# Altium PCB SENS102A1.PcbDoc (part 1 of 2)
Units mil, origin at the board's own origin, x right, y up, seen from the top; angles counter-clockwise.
Board outline 2760 x 2518.85 mil, 4 copper layers (Top Layer, Signal Layer 1, Signal Layer 2, Bottom Layer), stack 62.2 mil thick; 53 components, 21 nets, 101 pads, 383 vias.
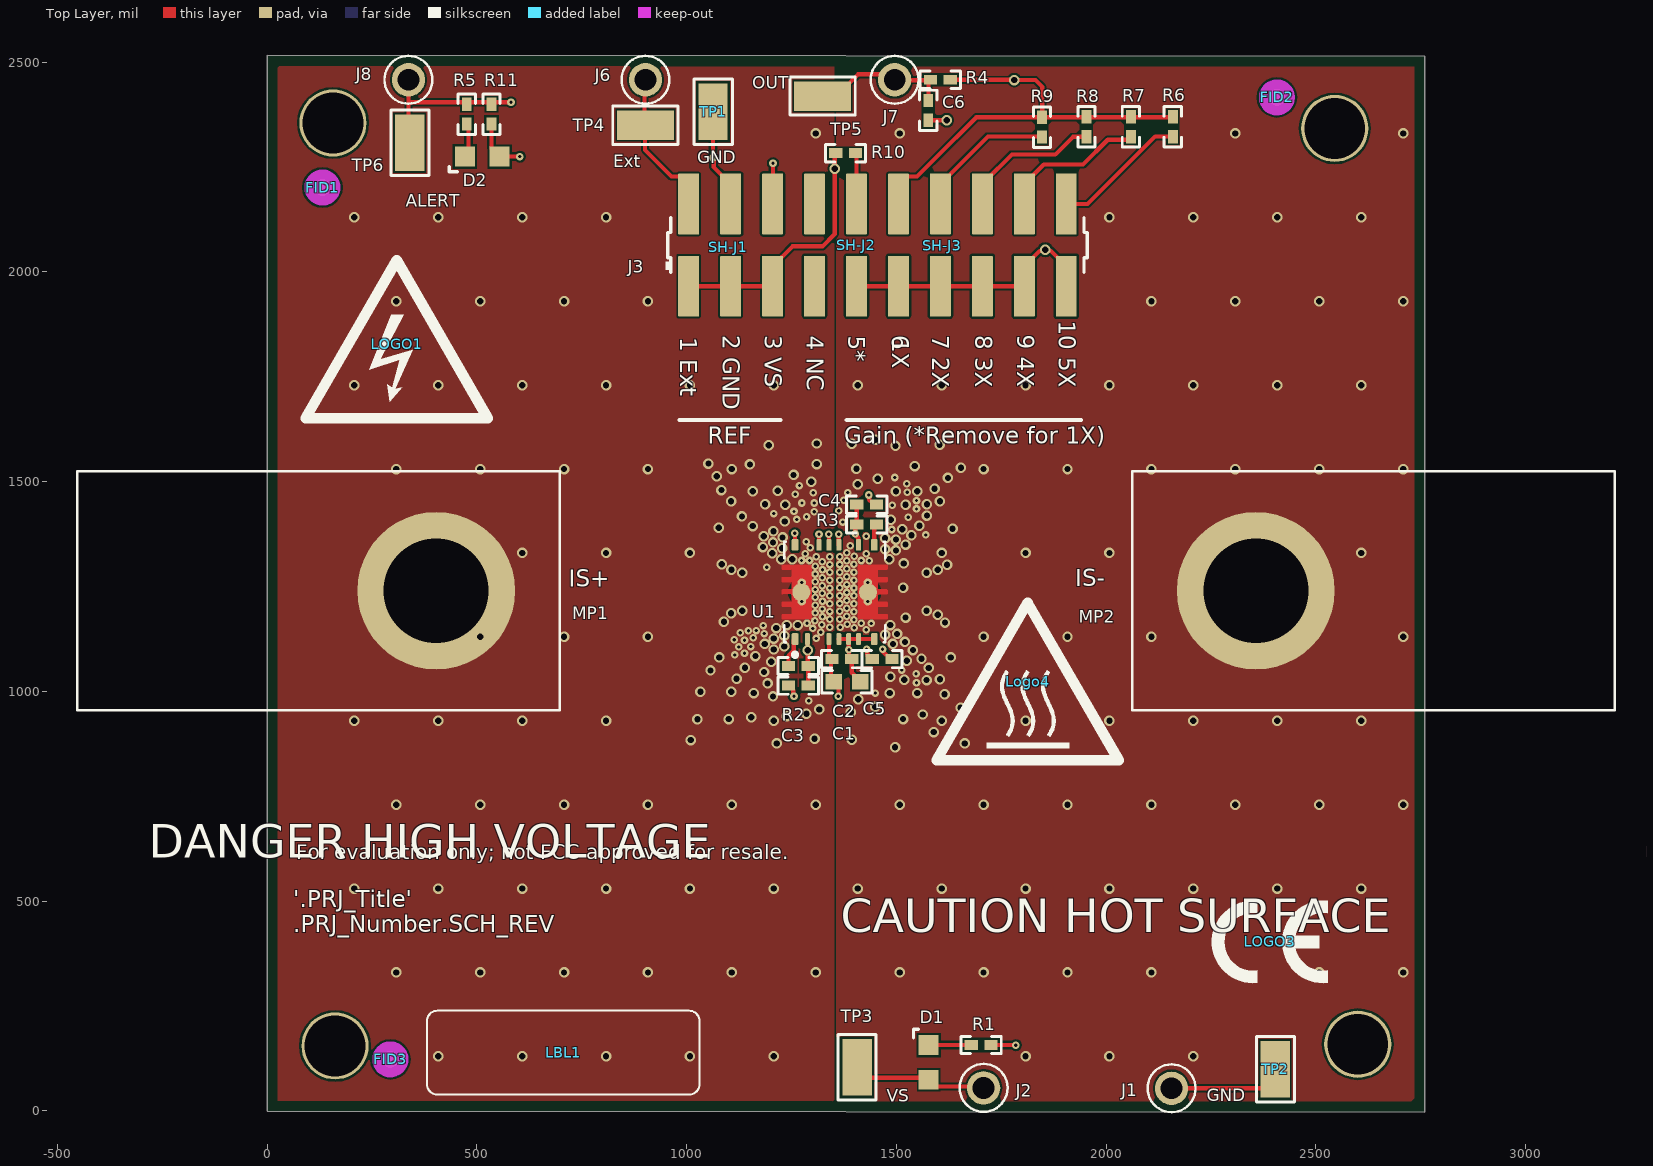
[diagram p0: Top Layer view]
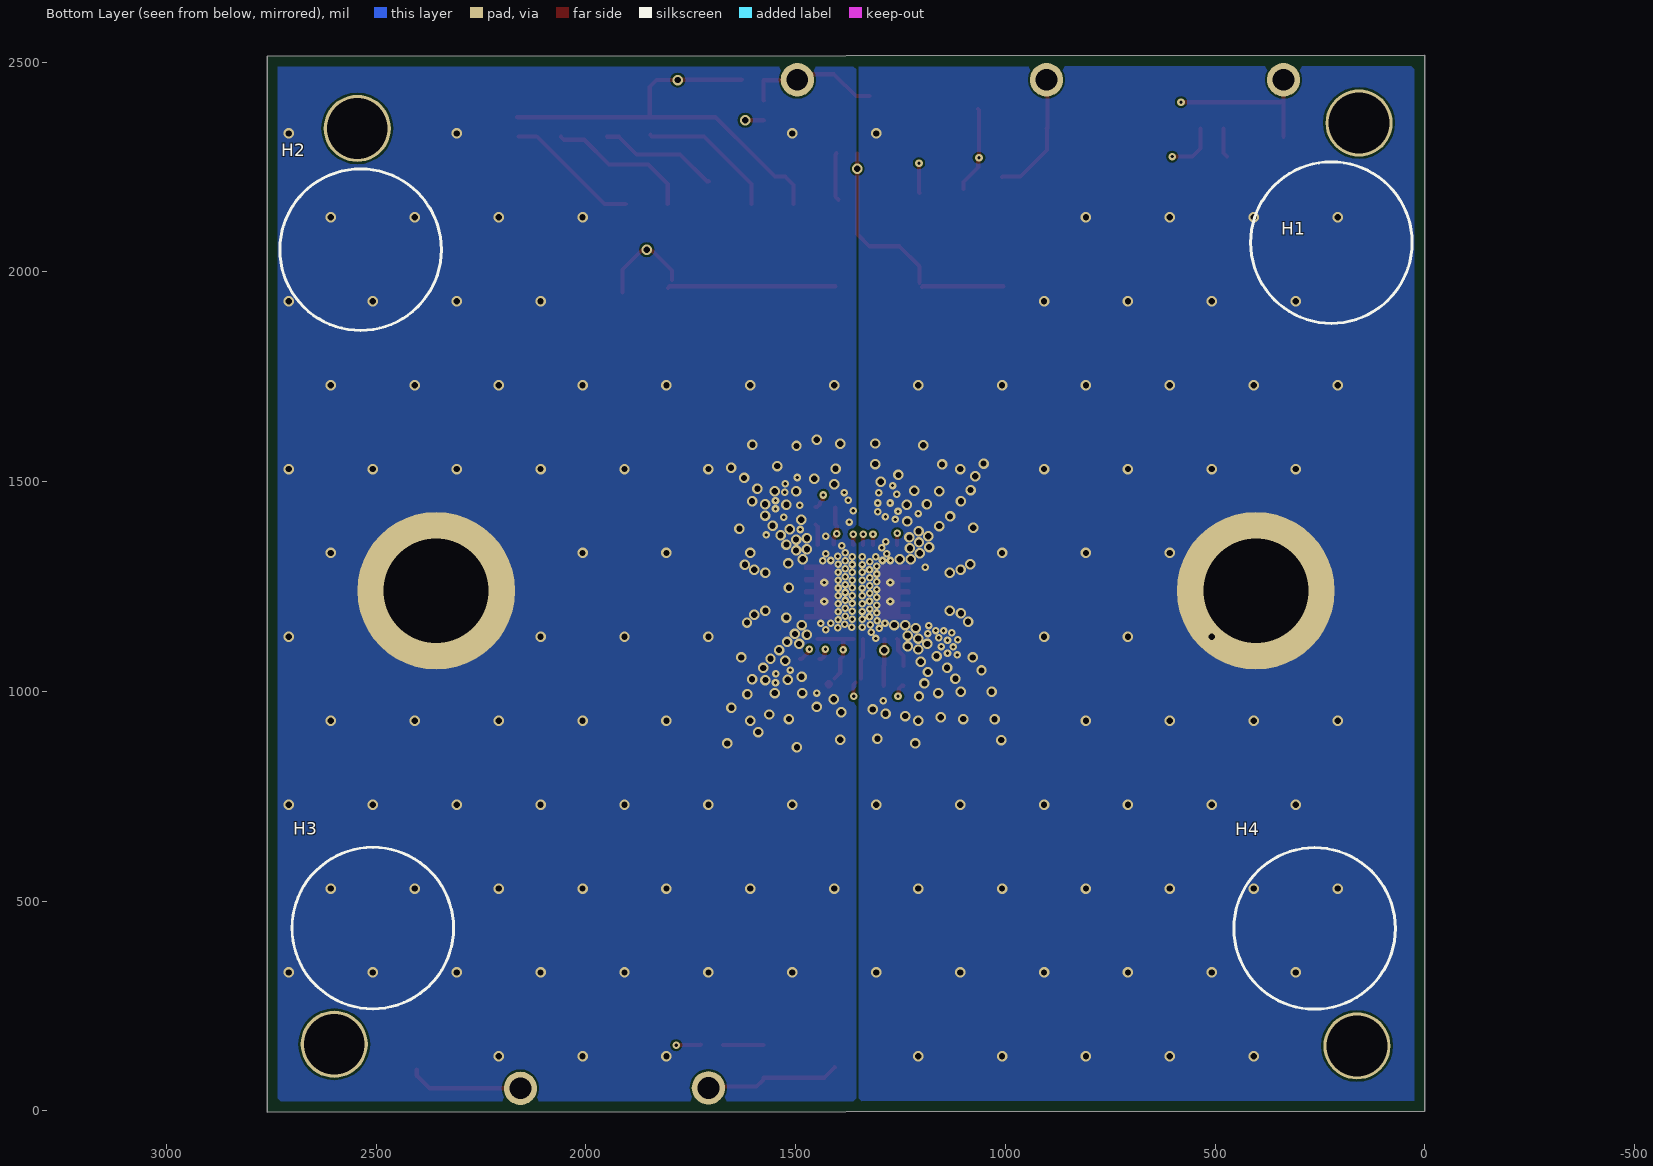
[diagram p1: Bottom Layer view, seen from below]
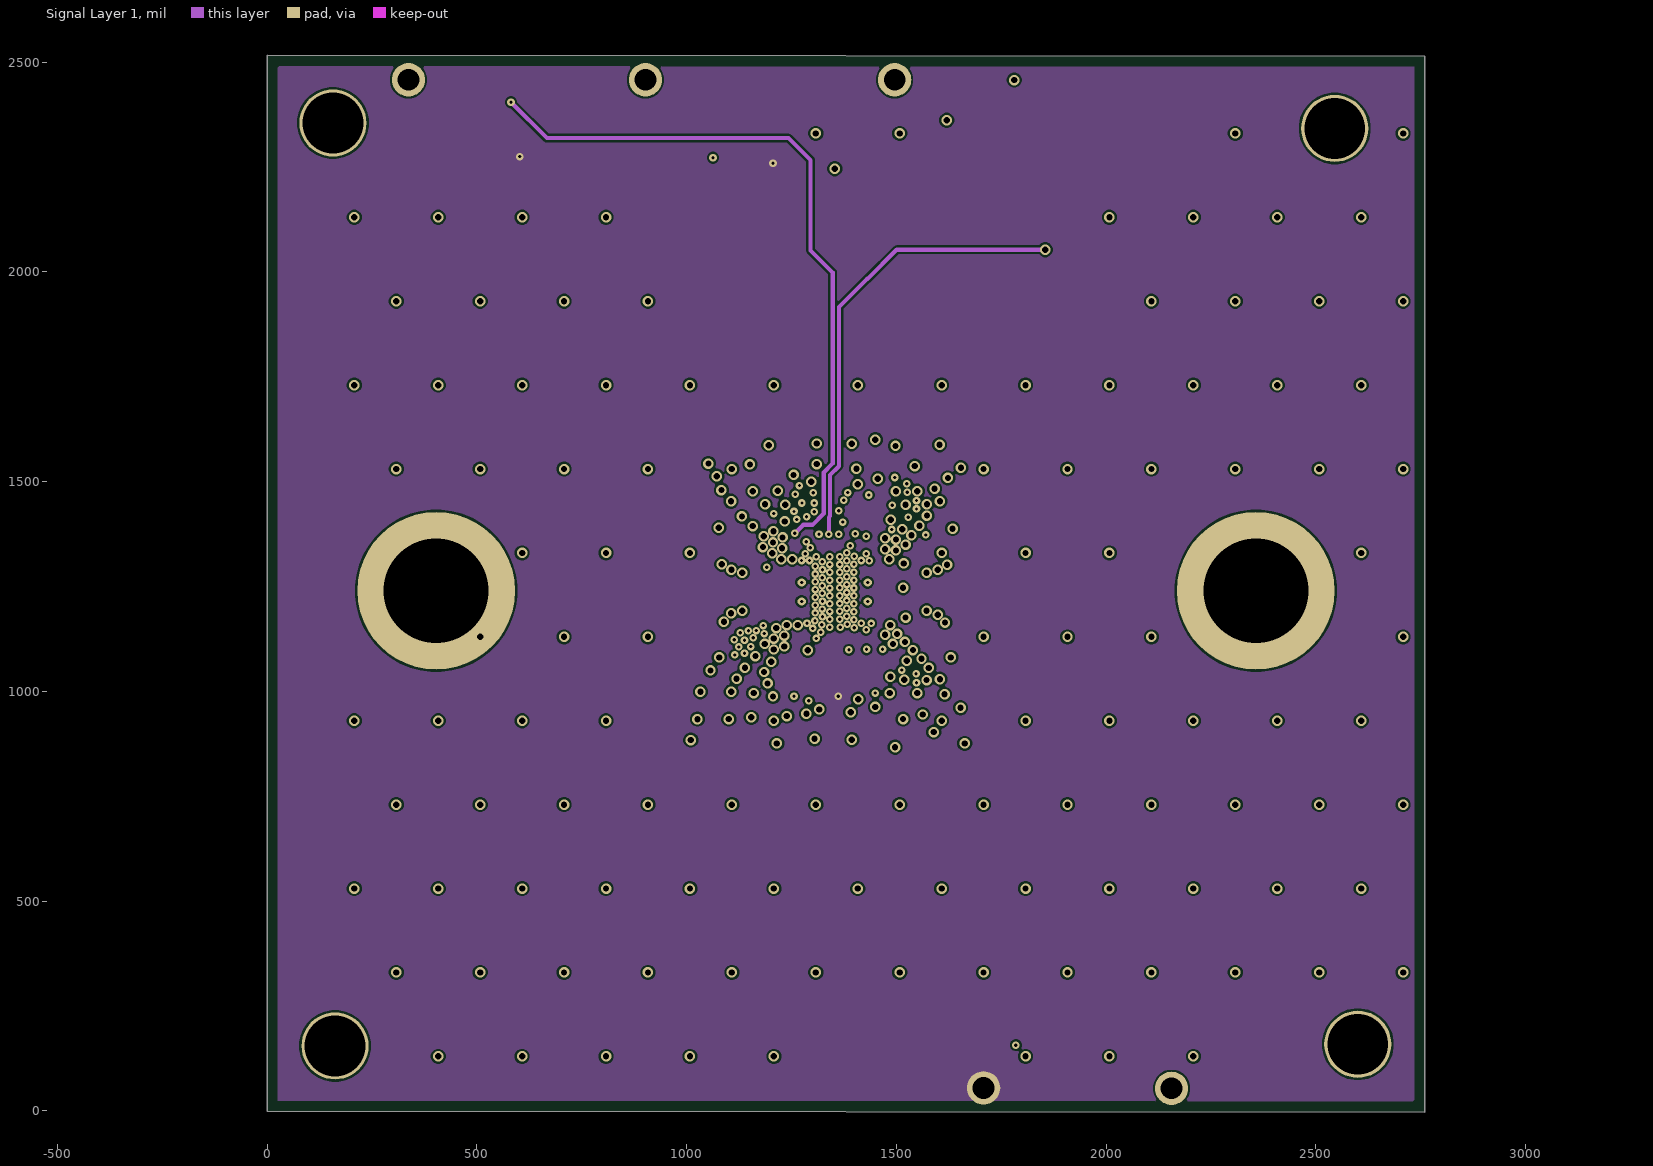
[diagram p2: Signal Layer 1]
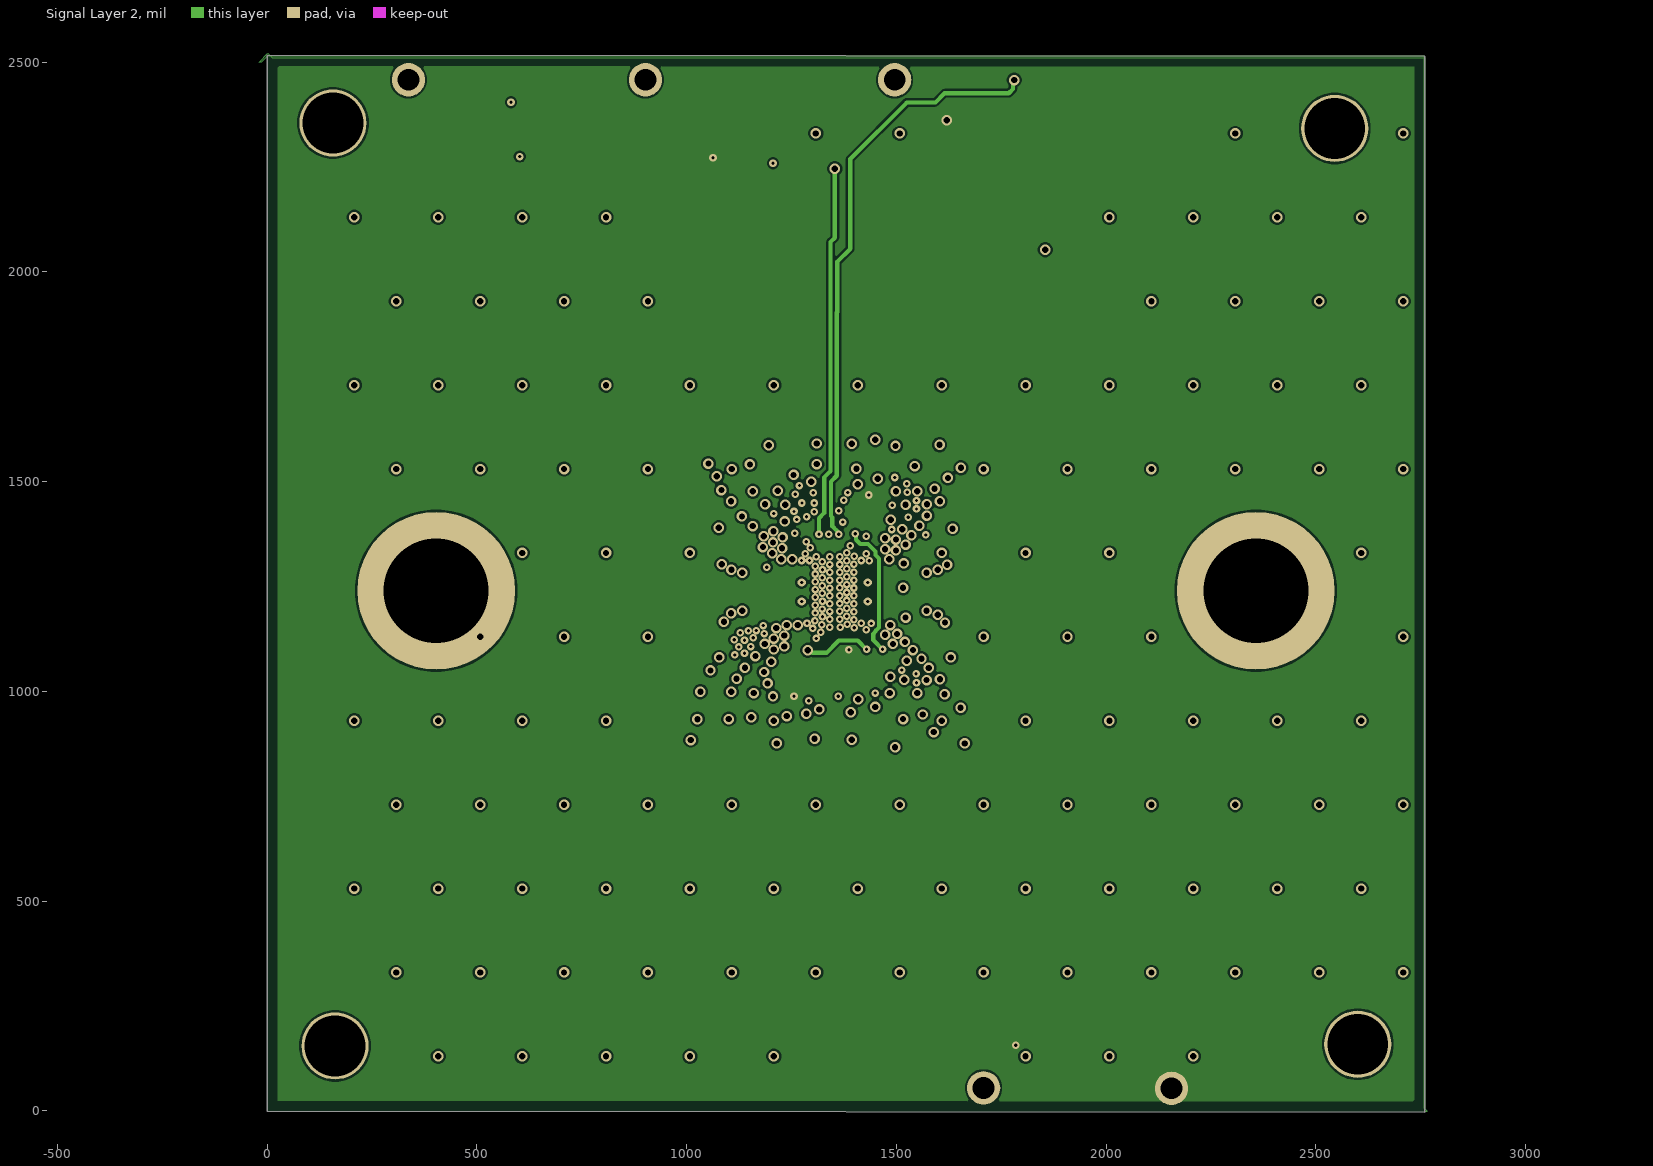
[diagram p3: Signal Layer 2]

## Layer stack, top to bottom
Top Solder: solder mask 0.4, Solder Resist, Dk 3.5
Top Layer: signal copper 2.8
Dielectric1: dielectric 17, FR-4, Dk 4.2
Signal Layer 1: signal copper 2.8
Dielectric 2: core 17, FR-4, Dk 4.2
Signal Layer 2: signal copper 2.8
Dielectric 3: dielectric 17, FR-4, Dk 4.2
Bottom Layer: signal copper 2.8
Bottom Solder: solder mask 0.4, Solder Resist, Dk 3.5

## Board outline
0,-1 0,2516 2760,2514.15 2760,-2.85

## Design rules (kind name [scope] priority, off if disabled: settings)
AcuteAngle [All] p1: minimum=4.50000000000000E+0001 checktracksonly=FALSE
AssemblyTestPointUsage [All] p1: valid=2
BoardOutlineClearance BoardOutlineClearance_MountingHoles [OnCopper and InComponentClass('Mounting Holes')] p1: gap=14 ignorepadtopadclearanceinfootprint=FALSE
BoardOutlineClearance BoardOutlineClearance_Poly [OnCopper and IsPoly] p2: gap=25 ignorepadtopadclearanceinfootprint=FALSE
BoardOutlineClearance [OnCopper and Not InComponentClass('Logo') and not InComponentClass('FiducialMark') and not InRegion(1000,500,4000,800) and not InPoly] p3: gap=15 ignorepadtopadclearanceinfootprint=FALSE
Clearance Clearance_Keepouts [((IsTrack Or IsArc) And Not InPoly) And IsFree and IsKeepOut vs ((IsTrack Or IsArc) And Not InPoly) And IsFree and IsKeepOut] p1: gap=0 ignorepadtopadclearanceinfootprint=FALSE
Clearance Clearance_IS+ [InNet('IS+') vs (InNet('+3V3') OR InNet('+5V') OR InNet('A0') OR InNet('A1') OR InNet('GND') OR InNet('NetD1_2') OR InNet('NetD2_2') OR InNet('NetU1_1') OR InNet('NetU1_7') OR InNet('NetU1_9') OR InNet('PD2') OR InNet('PN4') OR InNet('PN5') OR InNet('PP0'))] p2: gap=5.12 ignorepadtopadclearanceinfootprint=TRUE
Clearance Clearance_IS- [InNet('IS-') vs (InNet('+3V3') OR InNet('+5V') OR InNet('A0') OR InNet('A1') OR InNet('GND') OR InNet('NetD1_2') OR InNet('NetD2_2') OR InNet('NetU1_1') OR InNet('NetU1_7') OR InNet('NetU1_9') OR InNet('PD2') OR InNet('PN4') OR InNet('PN5') OR InNet('PP0'))] p3: gap=5.12 ignorepadtopadclearanceinfootprint=TRUE
Clearance Clearance_FiducialMark [IsKeepOut and InComponentClass('FiducialMark') vs IsPad and InComponentClass('FiducialMark')] p4: gap=0 ignorepadtopadclearanceinfootprint=FALSE
Clearance [All] p5: gap=5 ignorepadtopadclearanceinfootprint=TRUE
ComponentClearance ComponentClearance_MountingHoles_FiducialMarks [InComponentClass('Mounting Holes') vs InComponentClass('FiducialMark')] p1: gap=50 collisioncheckmode=3 verticalgap=10 showdistances=FALSE
ComponentClearance ComponentClearance_Shunt [InComponentClass('Header') vs InComponentClass('Shunt')] p2: gap=0 collisioncheckmode=3 verticalgap=0 showdistances=FALSE
ComponentClearance ComponentClearance_Logo [InComponentClass('Logo')] p3: gap=20 collisioncheckmode=3 verticalgap=10 showdistances=FALSE
ComponentClearance ComponentClearance_ScrewToNut [(HasFootprint('NY PMS 440 0025 PH')) vs (HasFootprint('Keystone_1902C'))] p4: gap=5 collisioncheckmode=3 verticalgap=10 showdistances=FALSE
ComponentClearance ComponentClearance_MountingHoles [InComponentClass('Mounting Holes')] p5: gap=250 collisioncheckmode=3 verticalgap=100000 showdistances=FALSE
ComponentClearance ComponentClearance_SmallPassives [HasFootprint('0201*') or HasFootprint('0402*') or HasFootprint('0508') or HasFootprint('0603*') or HasFootprint('0612') or HasFootprint('0805*') or HasFootprint('0815*') or HasFootprint('0830*') or HasFootprint('1206*') or HasFootprint('1210*') or HasFootprint('1808*') or HasFootprint('1812*') or HasFootprint('1825*') or HasFootprint('2010*') or HasFootprint('2220*') or HasFootprint('2225*') or HasFootprint('2512*') or HasFootprint('2728*') or HasFootprint('3518*') vs HasFootprint('0201*') or HasFootprint('0402*') or HasFootprint('0508') or HasFootprint('0603*') or HasFootprint('0612') or HasFootprint('0805*') or HasFootprint('0815*') or HasFootprint('0830*') or HasFootprint('1206*') or HasFootprint('1210*') or HasFootprint('1808*') or HasFootprint('1812*') or HasFootprint('1825*') or HasFootprint('2010*') or HasFootprint('2220*') or HasFootprint('2225*') or HasFootprint('2512*') or HasFootprint('2728*') or HasFootprint('3518*')] p6: gap=14.96 collisioncheckmode=3 verticalgap=10 showdistances=FALSE
ComponentClearance ComponentClearance_THtoSMT [IsThruComponent vs IsSMTComponent] p7: gap=40 collisioncheckmode=3 verticalgap=30 showdistances=FALSE
ComponentClearance ComponentClearance_THtoTH [IsThruComponent vs IsThruComponent] p8: gap=30 collisioncheckmode=3 verticalgap=30 showdistances=FALSE
ComponentClearance [All] p9: gap=30 collisioncheckmode=3 verticalgap=10 showdistances=FALSE
DiffPairsRouting [All] p1: maxlimit=100 minlimit=10 mostfreqgap=10 toplayer_minwidth=15 toplayer_maxwidth=15 toplayer_prefwidth=15 midlayer1_minwidth=15 midlayer1_maxwidth=15 midlayer1_prefwidth=15 midlayer2_minwidth=15 midlayer2_maxwidth=15 midlayer2_prefwidth=15 bottomlayer_minwidth=15 bottomlayer_maxwidth=15 bottomlayer_prefwidth=15 maxuncoupledlength=1000
FabricationTestPointUsage TestPointUsage [All] p1: valid=2 allowmultiple=FALSE
FabricationTestpoint Testpoint [All] p1: side=3 testpointundercomponent=TRUE minsize=40 maxsize=100 preferedsize=60 minholesize=0 maxholesize=40 preferedholesize=32 testpointgrid=1 allowsidetop=TRUE allowsidebottom=TRUE usegrid=TRUE gridtolerance=0.01
FanoutControl Fanout_LCC [IsLCC] p1: bgadir=Out bgaviamode=Centered fanoutstyle=Auto fanoutdirection=Alternating viagrid=1 // Fanout_LCC (Default Rule)
FanoutControl Fanout_BGA [IsBGA] p2: bgadir=Out bgaviamode=Centered fanoutstyle=Auto fanoutdirection=Alternating viagrid=1 // Fanout_BGA (Default Rule)
FanoutControl Fanout_Default [All] p4: bgadir=Out bgaviamode=Centered fanoutstyle=Auto fanoutdirection=Alternating viagrid=1 // Fanout_Default (Default Rule)
FanoutControl Fanout_Small [(CompPinCount < 5)] p5: bgadir=Out bgaviamode=Centered fanoutstyle=Auto fanoutdirection=OutThenIn viagrid=1 // Fanout_Small (Default Rule)
HoleSize [All] p1: absolutevalues=TRUE maxlimit=251 minlimit=8 maxpercent=80.000 minpercent=20.000
HoleToHoleClearance [All] p1: gap=8 allowstackedmicrovias=TRUE
MinimumAnnularRing MinimumAnnularRing_ThermalPadVias [IsVia and InAnyComponent] p1: minimumring=5
MinimumAnnularRing [All] p2: minimumring=5
MinimumSolderMaskSliver MinimumSolderMaskSliver_Logo [InComponentClass('Logo') vs InComponentClass('Logo')] p1: minsoldermaskwidth=0.7
MinimumSolderMaskSliver [All] p2: minsoldermaskwidth=4
PlaneConnect [All] p1: planeconnectstyle=Relief reliefexpansion=10 reliefentries=4 reliefconductorwidth=10 reliefairgap=10
PolygonConnect PolygonConnect_Trace [InNet('NetJ1_5') OR InNet('NetJ1_3')] p1: connectstyle=Direct reliefconductorwidth=10 reliefentries=4 polygonreliefangle="90 Angle" airgapwidth=10
PolygonConnect [All] p2: thpad.connectstyle=Direct thpad.reliefconductorwidth=10 thpad.reliefentries=4 thpad.polygonreliefangle="90 Angle" thpad.airgapwidth=10 smdpad.connectstyle=Relief smdpad.reliefconductorwidth=10 smdpad.reliefentries=2 smdpad.polygonreliefangle="90 Angle" smdpad.airgapwidth=10 via.connectstyle=Direct via.reliefconductorwidth=10 via.reliefentries=4 via.polygonreliefangle="90 Angle" via.airgapwidth=10
RoutingVias [All] p1: holewidth=10 width=20 viastyle="Through Hole" minholewidth=4 minwidth=15 maxholewidth=40 maxwidth=65
SilkToBoardRegionClearance [Not ((IsComment or IsDesignator) And (Hide <> 'False')) and not InRegion(1000,500,4000,800)] p1:
SilkToSilkClearance SilkToSilkClearance_Pb-FreeLogo [(HasFootprint('Pb-Free_Overlay_Medium') OR HasFootprint('Pb-Free_Overlay_Small')) vs (HasFootprint('Pb-Free_Overlay_Medium') OR HasFootprint('Pb-Free_Overlay_Small'))] p1: silktosilkclearance=0
SilkToSilkClearance [All] p2: silktosilkclearance=3.94
SilkToSolderMaskClearance SilkToComponentPadClearance [(IsPad or IsFill or IsRegion) and InAnycomponent] p1: minsilkscreentomaskgap=5 clearancetoexposedcopper=TRUE
SilkToSolderMaskClearance "Silk to Solder Mask Opening" [All] p2: minsilkscreentomaskgap=3.94 clearancetoexposedcopper=FALSE
SolderMaskExpansion [All] p1: expansion=1.97 istentingtop=FALSE
UnRoutedNet [All] p1: checkbadconnections=TRUE
Width [All] p1: maxlimit=100 minlimit=5 preferedwidth=10 checkconnectedcopper=TRUE
13 further rules are at their usual default settings.

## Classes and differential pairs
component class Label: LBL1
component class Shunt: SH-J1 SH-J2 SH-J3
component class Header: J3
component class SENS102E1: "ALERT BUS" C1 C2 C3 C4 C5 C6 D1 D2 J1 J2 J3 J6 J7 J8 MP1 MP2 q R1 R2 R3 R4 R5 R6 R7 R8 R9 R10 R11 SH-J1 SH-J2 SH-J3 SW2 SW? TP1 TP2 TP3 TP4 TP5 TP6 U1
component class SENS102E1_HW: FID1 FID2 FID3 H1 H2 H3 H4 LBL1 LOGO1 Logo2 LOGO3 Logo4 ZZ1 ZZ2 ZZ3 ZZ4
component class FiducialMark: FID1 FID2 FID3
component class AssemblyNote: ZZ1 ZZ2 ZZ3 ZZ4

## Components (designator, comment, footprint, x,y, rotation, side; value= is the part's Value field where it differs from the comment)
C1 "C1608X6S1H105K080AC" 0603 1382.19,1023 r0 top value=1uF
C2 "GRM155R71H104ME14D" 0402 1370,1077 r0 top value=0.1uF
C3 "CGA2B3X7S2A103K050BB" 0402 1266.25,1013.71 r180 top value=0.01uF
C4 "CGA2B3X7S2A103K050BB" 0402 1429.36,1445.12 r0 top value=0.01uF
C5 "CGA2B3X7S2A103K050BB" 0402 1466,1077 r0 top value=0.01uF
C6 "CGA2B3X7S2A103K050BB" 0402 1576,2385 r90 top value=0.01uF
D1 "POWER" VAOL-0805_White 1577,115.66 r90 top
D2 "ALERT" VAOL-0805_White 513,2275 r180 top
FID1 "Fiducial" Fiducial10-20 132,2201.12 r0 top
FID2 "Fiducial" Fiducial10-20 2407,2416 r0 top
FID3 "Fiducial" Fiducial10-20 294,123 r0 top
H1 "SJ61A2" Bumpon_SJ61A2 223,2070 r180 bottom
H2 "SJ61A2" Bumpon_SJ61A2 2537,2053 r180 bottom
H3 "SJ61A2" Bumpon_SJ61A2 2508,436 r180 bottom
H4 "SJ61A2" Bumpon_SJ61A2 263,435 r180 bottom
J1 "" FP-3-331272-8_PIN_RCPT-MFG 2156,54 r0 top
J2 "" FP-3-331272-8_PIN_RCPT-MFG 1708,55 r180 top
J3 "TSM-110-01-L-DV-P" CONN_TSM-110-01-T-DV-P 1455,2064 r90 top
J6 "" FP-3-331272-8_PIN_RCPT-MFG 902,2458 r0 top
J7 "" FP-3-331272-8_PIN_RCPT-MFG 1496,2458 r0 top
J8 "" FP-3-331272-8_PIN_RCPT-MFG 337,2458 r0 top
LBL1 "THT-14-423-10" Label_650x200 706,139 r180 top
LOGO1 "DANGER HIGH VOLTAGE" IEC_HighVoltage_Medium 309,1827 r0 top
Logo2 "FCC disclaimer" FCC_disclaimer 3340,617.12 r90 top
LOGO3 "CE Mark" CE_Mark_5mm 2390,403 r0 top
Logo4 "CAUTION HOT SURFACE" IEC_HotSurface_Medium 1813,1023 r0 top
MP1 "LAMA6-14-QY" FP-LAMA6-14-QY_TERMINAL_CONN-MFG 123,1240 r0 top
MP2 "LAMA6-14-QY" FP-LAMA6-14-QY_TERMINAL_CONN-MFG 2637,1240 r180 top
R1 "CRCW040210K0FKED" 0402 1702,157 r180 top value=10.0k
R2 "RC0402JR-070RL" 0402 1266.25,1060.71 r0 top value=0
R3 "RC0402JR-070RL" 0402 1429.36,1398 r180 top value=0
R4 "RC0402JR-070RL" 0402 1605,2458 r180 top value=0
R5 "CRCW040210K0FKED" 0402 476,2376 r90 top value=10.0k
R6 "CRCW040220K0FKED" 0402 2159,2346 r270 top value=20.0k
R7 "CRCW040215K0FKED" 0402 2059,2346 r270 top value=15.0k
R8 "CRCW040210K0FKED" 0402 1953,2346 r90 top value=10.0k
R9 "CRCW04024K99FKED" 0402 1847,2345 r270 top value=4.99k
R10 "CRCW04024K99FKED" 0402 1379,2283 r0 top value=4.99k
R11 "CRCW040210K0FKED" 0402 535,2376 r90 top value=10.0k
SH-J1 "SPC02SYAN" SPC02SYAN 1099,2059 r270 top value=1x2
SH-J2 "SPC02SYAN" SPC02SYAN 1404,2063 r90 top value=1x2
SH-J3 "SPC02SYAN" SPC02SYAN 1610,2062 r90 top value=1x2
TP1 "GND" Testpoint_Keystone_Miniature 1063,2382 r90 top
TP2 "GND" Testpoint_Keystone_Miniature 2403,99 r90 top
TP3 "VS" Testpoint_Keystone_Miniature 1407,104 r270 top
TP4 "Ext_REF" Testpoint_Keystone_Miniature 902,2350 r0 top
TP5 "OUT" Testpoint_Keystone_Miniature 1324,2419 r180 top
TP6 "" Testpoint_Keystone_Miniature 340,2308 r90 top
U1 "INA790AIDEKR" DEK0015A-MFG 1353,1237.12 r90 top
ZZ1 "This Assembly Note is for PCB labels only" AssemblyNoteLabel -115,3802.12 r0 top
ZZ2 "These assemblies are ESD sensitive, ESD precautions shall be observed." AssemblyNote -115,3693.24 r0 top
ZZ3 "These assemblies must be clean and free from flux and all contaminants. Use of no clean flux is not acceptable." AssemblyNote -115,3604.68 r0 top
ZZ4 "These assemblies must comply with workmanship standards IPC-A-610 Class 2, unless otherwise specified." AssemblyNote -115,3516.12 r0 top

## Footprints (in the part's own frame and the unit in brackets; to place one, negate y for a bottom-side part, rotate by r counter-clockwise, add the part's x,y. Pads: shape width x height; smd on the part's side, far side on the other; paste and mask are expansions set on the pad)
0402 [mm] "0402 from SM-752 data"
  rect 0.8x0.6 smd: 1(-0.6,0) 2(0.6,0)
  silkscreen extent -1.22,-0.52 1.22,0.52, body extent -0.55,-0.3 0.55,0.3, height 0.6
0603 [mm] "0603 from SM-752 data"
  rect 1x0.95 smd: 1(-0.8,0) 2(0.8,0)
  silkscreen extent -1.52,-0.69 1.52,0.69, body extent -0.87,-0.47 0.87,0.47, height 1
AssemblyNote [mil] "Assembly Note"
AssemblyNoteLabel [mil] "Assembly Note for PCB Labels"
Bumpon_SJ61A2 [mil] "3M Hemispherical Bumpon transparent"
  round 1 on Mech4: 0(0,0)
  silkscreen extent -192,-192 192,192, body extent -193,-193 193,193, height 250
CE_Mark_5mm [mil] "Minimum text height for CE Mark"
  silkscreen extent -138,-98 138,98
CONN_TSM-110-01-T-DV-P [mil]
  rrect8% 145x50 smd: 1(-98,450) 2(98,450) 3(-98,350) 4(98,350) 5(-98,250) 6(98,250) 7(-98,150) 8(98,150) 9(-98,50) 10(98,50) 11(-98,-50) 12(98,-50) 13(-98,-150) 14(98,-150) 15(-98,-250) 16(98,-250) 17(-98,-350) 18(98,-350) 19(-98,-450) 20(98,-450)
  silkscreen extent -65,-500 65,506, body extent -145,-500 145,500, height 380
DEK0015A-MFG [mm]
  rrect25% 0.7x0.4 smd paste+0 mask+0: 1(-2.85,2.4) 7(-2.85,-2.4) 9(2.85,-2.4) 14(2.85,2.4)
  rrect33% 0.7x0.3 smd paste+0 mask+0: 2(-2.85,1.65) 3(-2.85,0.35) 4(-2.85,-0.25) 5(-2.85,-0.85) 6(-2.85,-1.45) 10(2.85,-1.45) 11(2.85,-0.25) 12(2.85,0.35) 13(2.85,0.95)
  round 1.092 smd paste-1000 mask+0: 8(-0.019,-2.019) 15(-0.019,2.019)
  Top Layer region: 1.65,-3.15 1.643,-3.175 1.625,-3.193 1.6,-3.2 1.6,-3.2 1.4,-3.2 1.375,-3.193 1.357,-3.175 1.35,-3.15 1.35,-3.15 1.35,-2.65 1.346,-2.631 1.335,-2.615 1.319,-2.604 1.3,-2.6 1.3,-2.6 0.95,-2.6 0.931,-2.604 0.915,-2.615 0.904,-2.631 0.9,-2.65 0.9,-2.65 0.9,-3.15 0.893,-3.175 0.875,-3.193 0.85,-3.2 0.85,-3.2 0.65,-3.2 0.631,-3.196 0.615,-3.185 0.604,-3.169 0.6,-3.15 0.6,-3.15 0.6,-2.65 0.596,-2.631 0.585,-2.615 0.569,-2.604 0.55,-2.6 0.55,-2.6 0.2,-2.6 0.181,-2.604 0.165,-2.615 0.154,-2.631 0.15,-2.65 0.15,-2.65 0.15,-3.15 0.143,-3.175 0.125,-3.193 0.1,-3.2 0.1,-3.2 -0.1,-3.2 -0.125,-3.193 -0.143,-3.175 -0.15,-3.15 -0.15,-3.15 -0.15,-2.65 -0.154,-2.631 -0.165,-2.615 -0.181,-2.604 -0.2,-2.6 -0.2,-2.6 -0.55,-2.6 -0.569,-2.604 -0.585,-2.615 -0.596,-2.631 -0.6,-2.65 -0.6,-2.65 -0.6,-3.15 -0.604,-3.169 -0.615,-3.185 -0.631,-3.196 -0.65,-3.2 -0.65,-3.2 -0.85,-3.2 -0.869,-3.196 -0.885,-3.185 -0.896,-3.169 -0.9,-3.15 -0.9,-3.15 -0.9,-2.65 -0.904,-2.631 -0.915,-2.615 -0.931,-2.604 -0.95,-2.6 -0.95,-2.6 -1.3,-2.6 -1.319,-2.604 -1.335,-2.615 -1.346,-2.631 -1.35,-2.65 -1.35,-2.65 -1.35,-3.15 -1.354,-3.169 -1.365,-3.185 -1.381,-3.196 -1.4,-3.2 -1.4,-3.2 -1.6,-3.2 -1.625,-3.193 -1.643,-3.175 -1.65,-3.15 -1.65,-3.15 -1.65,-1.45 -1.643,-1.425 -1.625,-1.407 -1.6,-1.4 -1.6,-1.4 1.6,-1.4 1.625,-1.407 1.643,-1.425 1.65,-1.45 1.65,-1.45
  Top Layer region: -1.65,3.15 -1.643,3.175 -1.625,3.193 -1.6,3.2 -1.6,3.2 -1.4,3.2 -1.375,3.193 -1.357,3.175 -1.35,3.15 -1.35,3.15 -1.35,2.65 -1.346,2.631 -1.335,2.615 -1.319,2.604 -1.3,2.6 -1.3,2.6 -0.95,2.6 -0.931,2.604 -0.915,2.615 -0.904,2.631 -0.9,2.65 -0.9,2.65 -0.9,3.15 -0.893,3.175 -0.875,3.193 -0.85,3.2 -0.85,3.2 -0.65,3.2 -0.631,3.196 -0.615,3.185 -0.604,3.169 -0.6,3.15 -0.6,3.15 -0.6,2.65 -0.596,2.631 -0.585,2.615 -0.569,2.604 -0.55,2.6 -0.55,2.6 -0.2,2.6 -0.181,2.604 -0.165,2.615 -0.154,2.631 -0.15,2.65 -0.15,2.65 -0.15,3.15 -0.143,3.175 -0.125,3.193 -0.1,3.2 -0.1,3.2 0.1,3.2 0.125,3.193 0.143,3.175 0.15,3.15 0.15,3.15 0.15,2.65 0.154,2.631 0.165,2.615 0.181,2.604 0.2,2.6 0.2,2.6 0.55,2.6 0.569,2.604 0.585,2.615 0.596,2.631 0.6,2.65 0.6,2.65 0.6,3.15 0.604,3.169 0.615,3.185 0.631,3.196 0.65,3.2 0.65,3.2 0.85,3.2 0.869,3.196 0.885,3.185 0.896,3.169 0.9,3.15 0.9,3.15 0.9,2.65 0.904,2.631 0.915,2.615 0.931,2.604 0.95,2.6 0.95,2.6 1.3,2.6 1.319,2.604 1.335,2.615 1.346,2.631 1.35,2.65 1.35,2.65 1.35,3.15 1.354,3.169 1.365,3.185 1.381,3.196 1.4,3.2 1.4,3.2 1.6,3.2 1.625,3.193 1.643,3.175 1.65,3.15 1.65,3.15 1.65,1.45 1.643,1.425 1.625,1.407 1.6,1.4 1.6,1.4 -1.6,1.4 -1.625,1.407 -1.643,1.425 -1.65,1.45 -1.65,1.45
  silkscreen extent -3.92,-3.05 3.05,3.05, body extent -3.3,-3.3 3.3,3.3, height 0.25
FCC_disclaimer [mil]
Fiducial10-20 [mm]
  round 1 smd mask+0.5: 1(0,0)
  Top Layer keep-out circle w1.178: c0,0 r0.5
FP-3-331272-8_PIN_RCPT-MFG [mm]
  round 2.02 hole 1.32 paste-1000 mask+0: 1(0,0)
  silkscreen extent -1.45,-1.45 1.45,1.45, body extent -1.11,-1.11 1.11,1.11, height 0.25
FP-LAMA6-14-QY_TERMINAL_CONN-MFG [mm]
  round 9.55 hole 6.35 paste-1000 mask+0: 1(7.112,0)
  silkscreen extent -14.6,-7.24 14.6,7.24, body extent -14.32,-6.96 14.32,6.96, height 0.25
IEC_HighVoltage_Medium [mil]
  silkscreen extent -217,-176 217,200
IEC_HotSurface_Medium [mil]
  silkscreen extent -217,-188 217,188
Label_650x200 [mil] "Thermal Transfer Label"
  round 1 on Mech13: 0(0,0)
  silkscreen extent -325,-100 325,100, body extent -325,-100 325,100, height 1
SPC02SYAN [mil] "SULLINS"
  round 1 on Mech3: 0(0,0)
  body extent -98,-47 99,47, height 366
Testpoint_Keystone_Miniature [mil] "Miniature SMT test point"
  rect 135x70 smd: 1(0,0)
  silkscreen extent -78,-46 78,45, body extent -52,-20 52,20, height 61
VAOL-0805_White [mm] "Visual Communications"
  rect 1.2x1.2 smd: 1(-1.05,0) 2(1.05,0)
  silkscreen extent 1.5,0.63 2,0.91, body extent -1.05,-0.67 1.05,0.67, height 1.1

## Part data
C1: library part CMP-0007029-4, "CAP, CERM, 1 uF, 50 V, +/- 10%, X6S, 0603", Cap_Case=0603, Manufacturer=TDK, Supplier Part Number 1=445-7424-1-ND, TempCo=X6S, Tolerance_%=10%, Value1="0.005522 ohm", Value2=50V, ValueDisplayed=1uF
C2: library part CMP-0006675-2, "CAP, CERM, 0.1 uF, 50 V, +/- 20%, X7R, 0402", Cap_Case=0402, Manufacturer=MuRata, Supplier Part Number 1=490-10701-1-ND, TempCo=X7R, Tolerance_%=20%, Value1=Unknown, Value2=50V, ValueDisplayed=0.1uF
C3 C4 C5 C6: library part CMP-0006333-1, "CAP, CERM, 0.01 uF, 100 V, +/- 10%, X7S, AEC-Q200 Grade 1, 0402", Cap_Case=0402, Manufacturer=TDK, Supplier Part Number 1=445-6910-1-ND, TempCo=X7S, Tolerance_%=10%, Value1="0.410191 ohm", Value2=100V, ValueDisplayed=0.01uF
D1 D2: library part CMP-0002885-2, "LED, White, SMD", Color=White, Manufacturer="Visual Communications Company, LLC", PartNumber=VAOL-S8WR4, Value1=W, Value2=2.925V
FID1 FID2 FID3: library part CMP-0077181-1, "Fiducial mark.  There is nothing to buy or mount.", Manufacturer=N/A
H1 H2 H3 H4: library part CMP-0003622-1, "Bumpon, Hemisphere, 0.375 X 0.235, Black", Manufacturer=3M, Supplier Part Number 1=SJ5748-0-ND
J1 J2 J6 J7 J8: library part CMP-0086763-1, "CONN PIN RCPT .018-.021 SOLDER", Current_A=5A, Manufacturer="TE Connectivity", PartNumber=3-331272-8
J3: library part CMP-0075600-2, "Header, 2.54mm, 10x2, Gold, SMT", Color=Black, Current_A=5.4A, Manufacturer=Samtec, Supplier Part Number 1=SAM8739-ND, Voltage_V=475V
LBL1: library part CMP-0003625-1, "Thermal Transfer Printable Labels, 0.650\" W x 0.200\" H - 10,000 per roll", Manufacturer=Brady, Supplier Part Number 1=97C5133
LOGO1: library part CMP-0074835-1, "IEC 61010-1 High Voltage Warning"
Logo2: library part CMP-0074847-1, "FCC_disclaimer"
LOGO3: library part CMP-0074844-1
Logo4: library part CMP-0074837-2, "IEC 61010-1 Hot Surface Warning", Manufacturer="Texas Instruments"
MP1 MP2: library part CMP-0091352-2, "Terminal Connector Rectangular Lug, Grounding 6-14 AWG 1/4 Stud", Digikey Part Number=298-10102-ND, Manufacturer=Panduit, Mouser Part Number=644-LAMA6-14-QY, Operating Temperature Range=to
R1 R5 R8 R11: library part CMP-0025958-3, "RES, 10.0 k, 1%, 0.063 W, AEC-Q200 Grade 0, 0402", Manufacturer=Vishay-Dale, Power_W=63mW, Supplier Part Number 1=541-10.0KLCT-ND, TempCo="100 ppm/C", Tolerance_%=1%, Value2=0.063W, Value_Code=10k0, ValueDisplayed=10.0k
R2 R3 R4: library part CMP-0027004-2, "RES, 0, 5%, 0.063 W, 0402", Manufacturer="Yageo America", Power_W=63mW, Supplier Part Number 1=311-0.0JRCT-ND, TempCo="200 ppm/C", Tolerance_%=5%, Value2=0.063W, Value_Code=0000, ValueDisplayed=0
R6: library part CMP-0026162-1, "RES, 20.0 k, 1%, 0.063 W, 0402", Manufacturer=Vishay-Dale, Power_W=63mW, Supplier Part Number 1=541-20.0KLCT-ND, TempCo="100 ppm/C", Tolerance_%=1%, Value2=0.063W, Value_Code=20k0, ValueDisplayed=20.0k
R7: library part CMP-0026027-2, "RES, 15.0 k, 1%, 0.063 W, 0402", Manufacturer=Vishay-Dale, Power_W=63mW, Supplier Part Number 1=541-15.0KLCT-ND, TempCo="100 ppm/C", Tolerance_%=1%, Value2=0.063W, Value_Code=15k0, ValueDisplayed=15.0k
R9 R10: library part CMP-0026414-1, "RES, 4.99 k, 1%, 0.063 W, 0402", Manufacturer=Vishay-Dale, Power_W=63mW, Supplier Part Number 1=541-4.99KLCT-ND, TempCo="100 ppm/C", Tolerance_%=1%, Value2=0.063W, Value_Code=4k99, ValueDisplayed=4.99k
SH-J1 SH-J2 SH-J3: library part CMP-0003642-1, "Shunt, 100mil, Flash Gold, Black", Manufacturer="Sullins Connector Solutions", Supplier Part Number 1=S9001-ND
TP1 TP2 TP3 TP4 TP5 TP6: library part CMP-0055152-1, "Test Point, Miniature, SMT", Manufacturer=Keystone, PartNumber=5015, Supplier Part Number 1=36-5015TR-ND
U1: library part CMP-0034221-1, Manufacturer="Texas Instruments", Operating Temperature Range=to
ZZ1: library part CMP-0003616-3
ZZ2: library part CMP-0077236-1
ZZ3: library part CMP-0077237-1
ZZ4: library part CMP-0077238-1

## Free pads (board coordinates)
  round 160 hole 145: 3(157,2355) 3(162,155) 3(2545,2342.12) 3(2600,159)

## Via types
v1: diameter 25, hole 15, Top Layer to Bottom Layer, tented both sides, 247 vias
v2: diameter 18, hole 8, Top Layer to Bottom Layer, tented both sides, 132 vias
v3: diameter 19.68, hole 7.87, Top Layer to Bottom Layer, tented both sides, 4 vias

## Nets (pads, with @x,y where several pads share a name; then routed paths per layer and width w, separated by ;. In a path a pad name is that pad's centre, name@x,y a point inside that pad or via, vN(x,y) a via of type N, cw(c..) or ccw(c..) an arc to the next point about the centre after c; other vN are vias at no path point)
ALERT: J8.1 R5.2 R11.2 TP6.1 U1.14 | length 2129.6
  Top Layer w10: TP6.1@337,2322 337,2406 ; J8.1@337,2446 337,2406 ; v2(581.45,2404.5) 535,2404.5 480,2404.5 338.5,2404.5 337,2406 ; v2(1258,1377) 1258.26,1376.74 1258.26,1349.58 U1.14@1258.51,1349.33
  Signal Layer 1 w10: v2(581.45,2404.5) 666.95,2319 1243,2319 1295.59,2266.41 1295.59,2050.97 1348.19,1998.38 1348.19,1543 1327,1521.81 1327,1424.25 1299.87,1397.12 1278.12,1397.12 v2(1258,1377)
Ext_REF: J3.2 J6.1 TP4.1 | length 301.7
  Top Layer w10: TP4.1@900,2342 J6.1@900,2458 ; TP4.1@902,2342 901,2341 901,2290.32 963.82,2227.5 1006.5,2227.5 J3.2@1008,2226
FB: J3.9 J3.11 J3.13 J3.15 J3.17 J3.19 U1.12 | length 1760.8
  Top Layer w10: U1.12@1339.22,1349.33 v2(1339.22,1375) ; J3.9@1405,1966 J3.11@1505,1966 J3.13@1605,1966 J3.15@1705,1966 1800,1966 J3.17@1804,1962 ; J3.17@1795,1981 1795,2003.5 1841.63,2050.13 1852.13,2050.13 v1(1855,2053) 1857.87,2050.13 1868.37,2050.13 1913,2005.5 J3.19@1913,1951
  Signal Layer 1 w10: v2(1339.22,1375) 1339.22,1415.26 1342,1418.04 1342,1515.59 1363.19,1536.78 1363.19,1916.19 1430.5,1983.5 ; 1431,1983 1501,2053 v1(1855,2053)
GND: C1.2 C2.2 C3.2 C4.2 C6.1 J1.1 J3.4 R1.1 TP1.1 TP2.1 U1.4 U1.5 U1.6 U1.7 | length 845
  Top Layer w10: TP1.1@1065,2388 1063,2386 TP1.1@1063,2382 v2(1063,2272) 1064.53,2270.47 1064.53,2249.97 1100,2214.5 J3.4@1100,2198 ; C3.2@1242.62,1013.71 1246.56,1013.71 1253.37,1006.9 1253.37,1002.96 1254.47,1001.87 1254.47,989.72 v2(1256,988.19) ; U1.4@1362.92,1124.84 U1.4@1362.84,1124.92 U1.5@1386.46,1124.92 ; C1.2@1407.5,1031 1407.32,1031 1393.62,1044.7 C2.2@1393.62,1077 1387,1083.62 v2(1387,1099) 1386.73,1099.27 1386.73,1124.65 U1.5@1386.46,1124.92 ; v2(1434,1468.28) 1435.53,1466.75 1435.53,1456.73 1442.24,1450.02 1442.24,1446.09 1449.05,1439.28 C4.2@1452.99,1439.28 ; U1.7@1447.49,1124.92 U1.6@1410.09,1124.92 U1.5@1386.46,1124.92 ; C6.1@1576,2361.38 v1(1620,2361.38) ; R1.1@1726,158 1727,157 v2(1785,157) ; J1.1@2156,54 2373,54 2403,84 TP2.1@2403,99
  Top Layer w20: C1.2@1421,1016.68 C1.2@1421.66,1017.35
IN+: C3.1 C5.1 R2.2 U1.2 | length 291.7
  Top Layer w10: v1@1288.02,1099.4 U1.2@1288.04,1124.92 ; v1(1289,1098) 1289,1061.58 R2.2@1289.87,1060.71 C3.1@1289.87,1013.71 ; v2(1429,1100.27) 1430.53,1098.74 1430.53,1088.85 1431.63,1087.75 1431.63,1083.81 1438.44,1077 C5.1@1442.38,1077
  Signal Layer 2 w10: v1@1299.44,1092 1333.4,1092 1362.64,1121.24 1408.03,1121.24 v2(1429,1100.27)
IN-: C4.1 C5.2 R3.2 U1.10 | length 451.8
  Top Layer w10: C4.1@1405.74,1438 R3.2@1405.74,1398 1402,1394.26 v2(1402,1375.75) 1402,1373.58 1409.18,1366.4 U1.10@1409.18,1350.23 ; v2(1467.17,1100.27) 1468.7,1098.74 1468.7,1093.98 1485.68,1077 C5.2@1489.62,1077
  Signal Layer 2 w10: v2(1402,1375.75) 1403.53,1374.22 1403.53,1361.47 1413.88,1351.12 1432.18,1351.12 1450,1333.31 1450,1325 1458.5,1316.5 1458.5,1170.21 1458.85,1169.87 1458.85,1152.71 1450.58,1144.44 1450.58,1142.58 1445,1137 1445,1122.44 v2(1467.17,1100.27)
